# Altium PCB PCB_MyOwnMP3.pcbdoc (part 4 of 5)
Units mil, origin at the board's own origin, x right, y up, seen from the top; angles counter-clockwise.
Board outline 3605 x 4860 mil, 6 copper layers (Top Layer, Inner1, Inner2, Inner3, Inner4, Bottom Layer); 291 components, 261 nets, 1070 pads, 1658 vias.
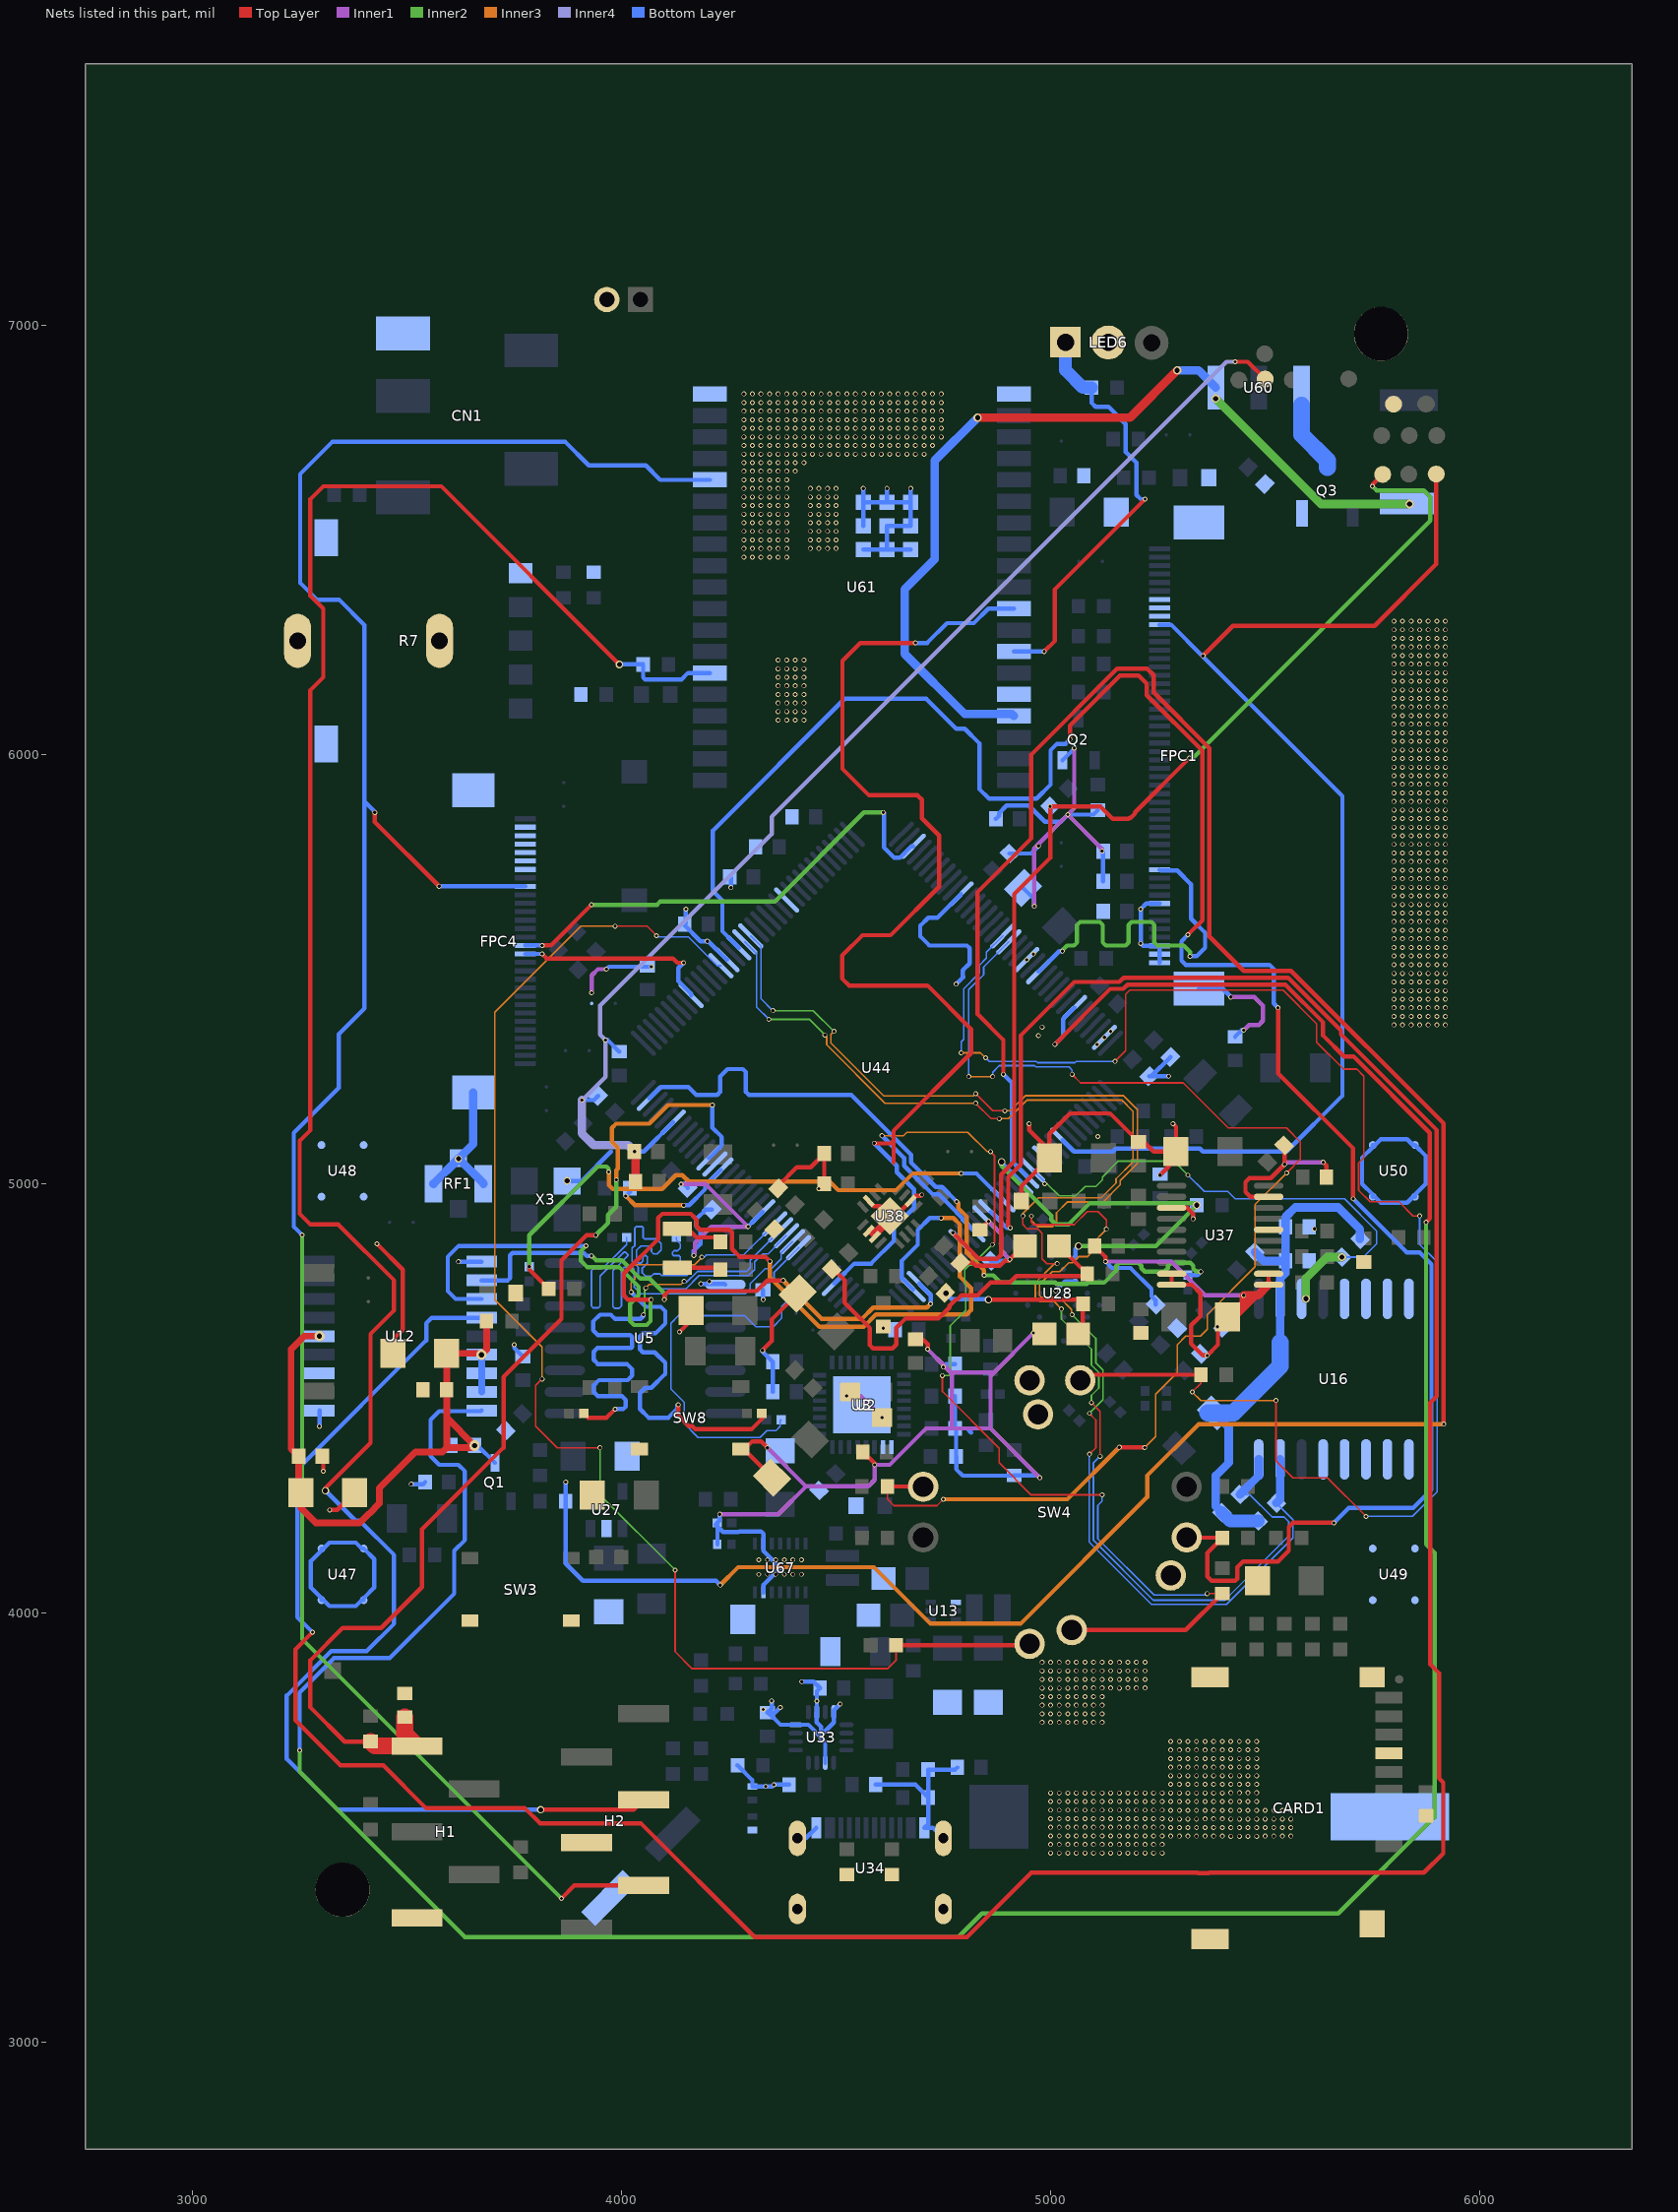
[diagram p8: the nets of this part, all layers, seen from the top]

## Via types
v1: diameter 11.42, hole 7.48, Top Layer to Bottom Layer, 1536 vias
v2: diameter 17.72, hole 11.81, Top Layer to Bottom Layer, 85 vias
v3: diameter 39.37, hole 29.53, Top Layer to Bottom Layer, 11 vias
v4: diameter 11.81, hole 7.87, Top Layer to Bottom Layer, 8 vias
v5: diameter 47.24, hole 23.62, Top Layer to Bottom Layer, 8 vias
v6: diameter 19.68, hole 11.81, Top Layer to Bottom Layer, 4 vias
v7: diameter 24.41, hole 12.2, Top Layer to Bottom Layer, 3 vias
v8: diameter 11.4, hole 7.5, Top Layer to Bottom Layer, 3 vias

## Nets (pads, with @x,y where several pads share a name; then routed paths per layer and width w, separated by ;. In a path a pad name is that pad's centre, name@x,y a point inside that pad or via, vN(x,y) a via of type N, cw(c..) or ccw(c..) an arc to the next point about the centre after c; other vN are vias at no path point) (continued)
GND: BAT1.1 C6.2 C7.2 C8.1 C9.2 C10.1 C11.2 C12.2 C13.1 C14.1 C15.1 C16.2 C17.2 C18.1 C19.2 C20.2 C21.2 C22.1 C25.1 C26.2 C28.1 C29.2 C30.2 C31.2 C32.1 C33.1 C34.2 C35.2 C37.2 C38.1 C39.1 C40.1 C41.2 C42.1 C43.1 C44.1 C45.1 C46.2 C47.2 C48.2 C49.2 C50.1 C51.1 C52.1 C53.1 C58.1 C59.1 C60.2 C61.2 C62.2 C63.2 C64.2 C65.2 C66.2 C67.2 C68.2 C69.2 C70.1 C71.2 C72.2 C75.1 C76.1 C77.1 C78.1 C79.1 C80.1 C81.1 C82.2 C84.1 C85.1 C114.1 C120.1 C121.2 C122.1 C123.2 C124.1 C126.1 C127.1 C129.1 C130.2 C131.1 C132.1 CARD1.6 CARD1.10 CARD1.11 CARD1.12 CARD1.13 CN1.1 D3.1 D4.1 FPC1.7 FPC1.8 FPC1.9 FPC1.43 FPC1.48 FPC1.49 FPC1.50 FPC1.51 FPC1.52 FPC4.24 FPC4.25 FPC4.26 FPC4.27 FPC4.28 FPC4.29 FPC4.31 FPC4.32 H1.1 H2.3 JP6.2 JP18.2 LED1.2 LED5.2 LED6.2 LED8.2 Q2.2 Q3.3 R5.2 R7.1 R7.6 R7.7 R25.1 R29.1 R32.1 R33.1 R36.1 R37.1 R40.2 R60.2 R98.2 R113.2 RF1.2 RF1.3 RF1.4 SCREW5.1 SCREW6.1 SW3.3 SW3.4 SW4.6 SW4.9 SW4.10 SW8.3 SW8.4 TP27.1 U2.2 U2.4 U3.1 U3.2 U3.33 U5.10 U6.1 U12.1 U12.10 U12.12 U13.4 U16.5 U16.6 U16.7 U16.8 U16.9 U16.10 U16.11 U16.12 U16.13 U17.2 U19.2 U20.1 U27.2 U28.B3 U30.1 U32.2 U33.4 U33.6 U33.8 U33.14 U33.17 U34.1 U34.2 U34.3 U34.4 U34.A1B12 U34.B1A12 U37.3 U37.9 U37.10 U37.11 U37.12 U37.16 U37.19 U38.2 U38.3 U38.10 U38.15 U38.17 U40.1 U44.16 U44.51 U44.61 U44.83 U44.94 U44.107 U44.120 U44.130 U47.1 U48.1 U49.1 U50.1 U61.1 U61.15 U61.38 U61.39 U67.2 U67.13 U67.15 X3.2 | length 13240.2
  Top Layer w10: C9.2@3302.56,4365 3305,4362.56 v1(3305,4330) ; v1(3320,4240) 3337.7,4240 C8.1@3377.7,4280 ; v1(3430,4860) 3490,4800 3490,4660 3467.3,4637.3 C6.2@3467.3,4605 ; v1(4135,4655) 4162.3,4682.3 C45.1@4162.3,4705 ; SW8.4@4278.11,4382.17 SW8.4@4284.16,4382.17 ; v1(4328.68,4611.61) 4328.68,4612.29 4350,4633.61 4350,4683.67 C44.1@4410.66,4744.34 ; v1(4340,4385) 4325,4400 4305,4400 4287.17,4382.17 SW8.4@4284.16,4382.17 ; C42.1@4350.66,4315.66 SW8.4@4284.16,4382.17 ; C15.1@4365.51,4989.49 4365.51,4995.51 4408.51,5038.51 4440.95,5038.51 C81.1@4472.44,5070 C84.1@4472.44,5000 ; C40.1@4562.44,4375 4562.44,4372.56 4573.31,4361.69 4576.91,4361.69 4590,4348.61 v1(4590,4345) ; U38.15@4576.32,4959.83 4576.32,4958.68 4587.33,4947.67 4602.34,4947.67 U38.17@4625.01,4925 ; C41.2@4685,4637.56 4702.44,4637.56 4713.54,4626.46 v1(4713.54,4614.61) ; v1(4700,4974.13) 4697.78,4971.92 4685.78,4971.92 U38.10@4673.69,4959.83 4638.86,4925 U38.17@4625.01,4925 ; C78.1@4789.49,4815.51 4819.49,4815.51 4825.98,4809.02 4881.62,4809.02 4893.29,4820.69 4901.81,4820.69 v1(4904.97,4823.85) 4936.12,4855 C77.1@4940.63,4855 ; C79.1@4835,4892.44 4835.39,4892.44 v1(4855.36,4912.41) ; LED5.2@4931.53,4960 4931.53,4994.23 C34.2@4997.3,5060 4997.3,5116.32 5045,5164.02 5138.54,5164.02 C33.1@5205,5097.56 5217.44,5097.56 5240,5075 C37.2@5292.3,5075 ; v1(4950,5140) 4950,5125 C34.2@4997.3,5077.7 ; v1(4960,4652.39) 4983.24,4652.39 C76.1@4985.63,4650 ; C35.2@5102.44,4855 5128.12,4829.32 v1(5128.12,4818.7) ; v1(5255,5020) 5292.3,5057.3 C37.2@5292.3,5075 ; U37.9@5281.97,4790.43 U37.10@5281.97,4764.84 5329.18,4764.84 5349.02,4745 5349.02,4691.5 5327.52,4670 5327.52,4627.48 5355,4600 v1(5365,4600) 5390,4625 5390,4665.42 v1(5388.52,4666.9) ; U37.3@5281.97,4943.98 5318.3,4943.98 5331.97,4930.3 v1(5331.97,4918.03) ; v1(5285,5140) 5292.3,5132.7 C37.2@5292.3,5075 ; C29.2@5417.7,4690 5433.19,4690 5468.35,4725.16 ; v1(5450,4740) 5464.84,4725.16 5468.35,4725.16 ; 5483.19,4740 5468.35,4725.16 ; U37.11@5508.03,4764.84 U37.12@5508.03,4790.43 ; U37.19@5508.03,4969.57 5465.43,4969.57 5453.94,4981.06 5453.94,5003.94 5463.31,5013.31 5513.31,5013.31 v1(5545,5045) 5545,5088.98 C75.1@5544.49,5089.49 ; v1(5635,5050) 5642.56,5042.44 C30.2@5642.56,5015 ; U38.17@4625.01,4925 4625.01,4911.14 U38.3@4590.18,4876.31 U38.2@4576.32,4890.17 4590.18,4890.17 U38.17@4625.01,4925
  Top Layer w19.68: C29.2@5417.7,4690 5450,4722.3 v1(5450,4740) 5483.19,4740 U37.11@5508.03,4764.84
  Inner1 w10: v1(3930.47,5444.84) 3930.47,5485.47 3945,5500 v1@3964.87,5500 ; v1(4138.75,4999.04) 4195.96,4999.04 v1(4295,4900) 4209.13,4900 4170.71,4861.59 4170.71,4835.36 v1(4168.31,4832.95) ; v1(4228.78,4230) 4365,4230 4430,4295 ; v1(4340,4385) 4430,4295 ; v1(4524.43,4505.72) 4557.15,4505.72 v1(4607.4,4455.47) ; v1(4713.54,4614.61) v1@4755.19,4572.95 ; v1(4749.88,4572.95) v1@4755.19,4572.95 ; v1(4855.36,4912.41) 4884.49,4883.28 4884.49,4844.33 v1(4904.97,4823.85) ; v1(4960,4652.39) 4867.45,4559.84 ; v1(4961.87,5646.29) 4961.87,5781.87 v1@4971.63,5791.63 ; v1(4971.63,5786.98) v1@4971.63,5791.63 ; v1(4975,4315) 4860,4430 ; v1(5055,6015) 5055,5875 v1(5040,5860) ; v1(5120,5775) 5120,5780 v1(5040,5860) ; v1(5128.12,4818.7) 5281.3,4818.7 5360,4740 v1(5450,4740) ; v1(5420,5435) 5475,5435 5495,5415 5495,5380 5485,5370 5462.07,5370 v1(5450,5357.93) ; v1(5545,5045) 5550,5050 v1(5635,5050) ; 4430,4295 4575,4295 4590,4310 v1(4590,4345) 4625,4345 4710,4430 4770.17,4430 ; v1@4755.19,4572.95 4770.17,4557.97 ; 4770.17,4430 4770.17,4557.97 ; 4770.17,4430 4860,4430 ; 4770.17,4557.97 4772.05,4559.84 4860,4559.84 ; 4860,4430 4860,4552.39 ; 4860,4552.39 4860,4559.84 ; 4860,4552.39 4867.45,4559.84 ; 4860,4559.84 4867.45,4559.84 ; v1@4971.63,5791.63 v1(5040,5860)
  Bottom Layer w10: v1(3296.02,4435) U12.10@3296.02,4471.77 ; U47.1@3399.19,4150.18 3394.45,4150.17 3380.64,4163.98 3319.36,4163.98 3305.55,4150.17 U47.1@3300.79,4150.17 3300.79,4145.41 3276.02,4120.64 3276.02,4059.36 3300.79,4034.59 U47.1@3300.79,4029.83 3305.55,4029.83 3319.36,4016.02 3380.64,4016.02 3394.45,4029.83 U47.1@3399.21,4029.83 3399.21,4034.59 3423.98,4059.36 3423.98,4125.39 U47.1@3399.19,4150.18 ; v1(3510,4300) 3537.44,4300 C21.2@3542.44,4305 ; v1(3620,4818.23) U12.1@3673.98,4818.23 ; v1(3750,4625) 3750,4617.56 C22.1@3770,4597.56 ; v2(3873.31,5006.62) 3907.09,5006.62 JP18.2@3975.47,5075 ; v1(3964.93,5499.93) 3970.59,5505.59 v1(4069.6,5505.59) ; v1(4138.75,4999.04) 4145.96,4999.04 C64.2@4154.49,4990.51 ; v1(4150,5640) 4150,5607.56 C63.2@4147.44,5605 4147.44,5601.8 4184.24,5565 v1(4200,5565) 4202.56,5565 U44.51@4245.62,5521.94 ; v1(4168.31,4832.95) 4168.31,4843.97 4184.16,4859.82 4184.16,4890.18 4175,4899.34 4175.09,4918.78 4195.8,4939.49 C65.2@4210.51,4939.49 ; v1(4185,4766.69) 4240.34,4766.69 U5.10@4242.02,4765.01 ; C127.1@4223.46,4160 R113.2@4223.46,4201.54 ; v1(4228.78,4230) 4228.78,4215.82 R113.2@4222.96,4210 R113.2@4223.46,4209.5 ; C62.2@4252.44,5715 4255,5712.44 v1(4255,5690) ; U20.1@4270.34,3645 4305,3610.34 D3.1@4305,3595.75 v1(4335.73,3595.75) 4350.75,3595.75 v1(4355,3600) U6.1@4390.34,3600 ; v1(4295,4900) 4329.13,4934.13 U44.16@4329.13,4934.54 ; v1(4328.68,4611.61) 4328.68,4608.76 C46.2@4352.44,4585 C43.1@4352.44,4515 ; v1(4330,4730) C58.1@4330,4752.56 ; U67.13@4330.63,4047.91 4330.63,4065.63 U67.15@4370,4105 4330.63,4144.37 U67.2@4330.63,4162.09 4330.63,4184.37 4325,4190 4274.34,4190 4272.72,4188.39 4236.61,4188.39 R113.2@4223.46,4201.54 ; v1(4350,3795) 4350,3777.56 C85.1@4340,3767.56 C85.1@4342.44,3767.56 ; v1(4370,3780) 4357.56,3767.56 C85.1@4342.44,3767.56 ; U34.2@4409.92,3475.08 4429.61,3475.08 U34.B1A12@4454.02,3499.49 ; v1(4420,3840) 4447.44,3840 C51.1@4462.44,3825 4455.17,3817.73 v1(4455.17,3794.75) U33.6@4455.17,3769.05 4455,3768.88 4455,3745 4465.01,3734.99 U33.17@4465.01,3715.02 ; U33.14@4474.85,3650.94 4474.85,3700.15 U33.17@4465.01,3709.99 ; v1(4509.54,3787.69) 4495,3773.15 4495,3745.01 U33.17@4465.01,3715.02 ; U61.39@4563.54,6477.4 U61.39@4618.66,6477.4 ; U61.39@4563.54,6532.52 U61.39@4563.54,6587.64 ; v1(4563.54,6620) U61.39@4563.54,6587.64 ; C50.1@4592.56,3600 4685,3600 R32.1@4714.66,3570.34 ; v1(4618.66,6620) U61.39@4618.66,6587.64 ; U61.39@4673.78,6477.4 U61.39@4618.66,6477.4 ; v1(4673.78,6620) U61.39@4673.78,6587.64 ; v1(4749.88,4572.95) 4756.93,4580 C47.2@4777.56,4580 ; U34.1@4750.08,3475.08 4725.67,3499.49 U34.A1B12@4705.99,3499.49 4714.66,3508.16 R32.1@4714.66,3570 R32.1@4714.66,3570.34 ; C80.1@4777.56,4505 C49.2@4777.56,4430 ; v1(4780,5465) 4796.06,5481.06 4796.06,5482.65 4795.63,5483.09 4795.63,5496.91 4796.06,5497.35 4796.06,5498 4811.22,5513.16 4811.22,5548.78 4805,5555 4717.61,5555 4695.98,5576.62 4695.98,5601.16 4714.82,5620 4736.21,5620 U44.83@4791.27,5675.06 ; C12.2@4782.44,3640 4777.44,3635 R33.1@4714.66,3635 R32.1@4714.66,3570.34 ; 4815,4420 4805,4430 C49.2@4777.56,4430 ; C67.2@4860.51,4820.51 4901.53,4820.51 4901.7,4820.69 4901.81,4820.69 v1(4904.97,4823.85) ; C122.1@4872.44,5850 4880,5857.56 4880,5863.56 4897.5,5881.06 4948.94,5881.06 4986.61,5843.39 5023.39,5843.39 v1(5040,5860) 5099.66,5860 R60.2@5110,5870.34 ; C123.2@4904.49,5769.49 4954.13,5769.49 v1(4971.63,5786.98) ; C25.1@4935.66,5689.34 4961.87,5663.13 v1(4961.87,5646.29) ; v1(4975,4315) 4969.66,4320.34 U40.1@4915,4320.34 4914.66,4320 4795,4320 4780,4335 4780,4364.66 R29.1@4779.66,4365 4779.66,4427.9 C49.2@4777.56,4430 ; v1(5012.01,4750.23) 5012.72,4750.94 5012.72,4752.16 5022.84,4762.28 5023.04,4762.28 5033.6,4772.84 U28.B3@5057.84,4772.84 ; Q2.2@5027.6,5986.38 5055,6013.78 v1(5055,6015) ; v1(5120,5775) 5122.44,5772.56 C19.2@5122.44,5705 ; v1(5128.12,4818.7) 5142.81,4804.02 5185.98,4804.02 5235,4755 5235,4738.22 5244.77,4728.45 C71.2@5244.77,4718.45 ; C60.2@5229.49,5250.51 C60.2@5234.49,5250.51 ; FPC1.50@5254.25,5515.15 FPC1.49@5254.24,5534.82 FPC1.48@5254.25,5554.5 5215.5,5554.5 v1(5210,5560) v1(5210,5640) 5222.89,5652.89 FPC1.43@5254.3,5652.89 ; v1(5275,5250.51) C60.2@5234.49,5250.51 ; C52.1@5279.49,5295.51 C60.2@5234.49,5250.51 ; FPC1.52@5345.88,5454.46 5400.54,5454.46 v1(5420,5435) ; C59.1@5430,5342.56 5445.37,5357.93 v1(5450,5357.93) ; U50.1@5849.19,5090.18 5844.45,5090.17 5830.64,5103.98 5769.36,5103.98 5755.55,5090.17 U50.1@5750.79,5090.17 5750.79,5085.41 5726.02,5060.64 5726.02,4999.36 5750.79,4974.59 U50.1@5750.79,4969.83 5755.55,4969.83 5769.36,4956.02 5830.64,4956.02 5844.45,4969.83 U50.1@5849.21,4969.83 5849.21,4974.59 5873.98,4999.36 5873.98,5065.39 U50.1@5849.19,5090.18 ; R113.2@4223.46,4201.54 4219.48,4205.52 R113.2@4223.46,4209.5 ; R113.2@4223.46,4201.54 R113.2@4223.46,4209.5 ; C85.1@4342.44,3767.56 4370.48,3739.52 U33.4@4405.95,3739.52 4435.48,3739.52 U33.17@4465.01,3709.99 ; U33.17@4465.01,3709.99 U33.17@4465.01,3715.02 ; U61.39@4563.54,6587.64 U61.39@4618.66,6587.64 ; U61.39@4618.66,6477.4 U61.39@4618.66,6532.52 U61.39@4673.78,6532.52 U61.39@4673.78,6587.64 ; U61.39@4618.66,6587.64 U61.39@4673.78,6587.64
  Bottom Layer w19.68: RF1.2@3561.93,5000 v2(3620,5058.07) ; FPC4.32@3654.47,5213.04 3654.47,5092.54 RF1.4@3620.49,5058.56 ; RF1.3@3678.07,5000 3678.07,5000.98 RF1.4@3620.49,5058.56 ; v2(3620,5058.07) RF1.4@3620,5059.05 RF1.4@3620.49,5058.56 ; v2(3620,5058.07) RF1.4@3620.49,5058.56
  other v1: 5000,3440.67 5020,3440.67 5040,3440.67 5060,3440.67 5080,3440.67 5100,3440.67 5120,3440.67 5140,3440.67 5160,3440.67 5180,3440.67 5200,3440.67 5220,3440.67 5240,3440.67 5260,3440.67 5000,3460.67 5020,3460.67 5040,3460.67 5060,3460.67 5080,3460.67 5100,3460.67 5120,3460.67 5140,3460.67 5160,3460.67 5180,3460.67 5200,3460.67 5220,3460.67 5240,3460.67 5260,3460.67 5280,3480 5300,3480 5320,3480 5340,3480 5360,3480 5380,3480 5400,3480 5420,3479.77 5440,3479.77 5460,3479.77 5480,3479.77 5500,3480 5520,3480 5540,3480 5560,3480 5000,3480.67 5020,3480.67 5040,3480.67 5060,3480.67 5080,3480.67 5100,3480.67 5120,3480.67 5140,3480.67 5160,3480.67 5180,3480.67 5200,3480.67 5220,3480.67 5240,3480.67 5260,3480.67 5280,3500 5300,3500 5320,3500 5340,3500 5360,3500.23 5380,3500.23 5400,3500.23 5420,3499.77 5440,3499.77 5460,3499.77 5480,3499.77 5500,3500 5520,3500 5540,3500 5560,3500 5000,3500.67 5020,3500.67 5040,3500.67 5060,3500.67 5080,3500.67 5100,3500.67 5120,3500.67 5140,3500.67 5160,3500.67 5180,3500.67 5200,3500.67 5220,3500.67 5240,3500.67 5260,3500.67 5280,3520 5300,3520 5320,3520 5340,3520 5360,3520.23 5380,3520.23 5400,3520.23 5420,3519.77 5440,3519.77 5460,3519.77 5480,3519.77 5500,3520 5520,3520 5540,3520 5560,3520 5000,3520.67 5020,3520.67 5040,3520.67 5060,3520.67 5080,3520.67 5100,3520.67 5120,3520.67 5140,3520.67 5160,3520.67 5180,3520.67 5200,3520.67 5220,3520.67 5240,3520.67 5260,3520.67 5280,3540 5300,3540 5320,3540 5340,3540 5360,3540.23 5380,3540.23 5400,3540.23 5420,3540 5440,3540 5460,3540 5480,3540 5500,3540 5520,3540 5540,3540 5560,3540 5000,3540.67 5020,3540.67 5040,3540.67 5060,3540.67 5080,3540.67 5100,3540.67 5120,3540.67 5140,3540.67 5160,3540.67 5180,3540.67 5200,3540.67 5220,3540.67 5240,3540.67 5260,3540.67 5000,3560.67 5020,3560.67 5040,3560.67 5060,3560.67 5080,3560.67 5100,3560.67 5120,3560.67 5140,3560.67 5160,3560.67 5180,3560.67 5200,3560.67 5220,3560.67 5240,3560.67 5260,3560.67 5280,3560.67 5300,3560.67 5320,3560.67 5340,3560.67 5360,3560.67 5380,3560.67 5400,3560.67 5419.96,3560.91 5439.96,3560.91 5459.96,3560.91 5479.96,3560.91 5000,3580.67 5020,3580.67 5040,3580.67 5060,3580.67 5080,3580.67 5100,3580.67 5120,3580.67 5140,3580.67 5160,3580.67 5180,3580.67 5200,3580.67 5220,3580.67 5240,3580.67 5260,3580.67 5280,3580.67 5300,3580.67 5320,3580.67 5340,3580.67 5360,3580.67 5380,3580.67 5400,3580.67 5419.96,3580.91 5439.96,3580.91 5459.96,3580.91 5479.96,3580.91 5280,3600.67 5300,3600.67 5320,3600.67 5340,3600.67 5360,3600.67 5380,3600.67 5400,3600.67 5419.96,3600.91 5439.96,3600.91 5459.96,3600.91 5479.96,3600.91 5280,3620.67 5300,3620.67 5320,3620.67 5340,3620.67 5360,3620.67 5380,3620.67 5400,3620.67 5419.96,3620.91 5439.96,3620.91 5459.96,3620.91 5479.96,3620.91 5280,3640.67 5300,3640.67 5320,3640.67 5340,3640.67 5360,3640.67 5380,3640.67 5400,3640.67 5419.73,3640.91 5439.73,3640.91 5459.73,3640.91 5479.96,3640.91 5280,3660.67 5300,3660.67 5320,3660.67 5340,3660.67 5360,3660.67 5380,3660.67 5400,3660.67 5419.73,3660.91 5439.73,3660.91 5459.73,3660.91 5479.96,3660.91 5280,3680.67 5300,3680.67 5320,3680.67 5340,3680.67 5360,3680.67 5380,3680.67 5400,3680.67 5419.73,3680.91 5439.73,3680.91 5459.73,3680.91 5479.96,3680.91 5280,3700.67 5300,3700.67 5320,3700.67 5340,3700.67 5360,3700.67 5380,3700.67 5400,3700.67 5419.73,3700.91 5439.73,3700.91 5459.73,3700.91 5479.96,3700.91 4980,3745 5000,3745 5020,3745 5040,3745 5060,3745 5080,3745 5100,3745 5120,3745 4980,3765 5000,3765 5020,3765 5040,3765 5060,3765 5080,3765 5100,3765 5120,3765 4330,3775 4980,3785 5000,3785 5020,3785 5040,3785 5060,3785 5080,3785 5100,3785 5120,3785 4980,3805 5000,3805 5020,3805 5040,3805 5060,3805 5080,3805 5100,3805 5120,3805 4980,3825 5000,3825 5020,3825 5040,3825 5060,3825.23 5080,3825.23 5100,3825.23 5120,3825.23 5140,3825.23 5160,3825 5180,3825.23 5200,3825.23 5220,3825.23 4980,3845 5000,3845 5020,3845 5040,3845 5060,3845.23 5080,3845.23 5100,3845.23 5120,3845.23 5140,3845.23 5160,3845 5180,3845.23 5200,3845.23 5220,3845.23 4980,3865 5000,3865 5020,3865 5040,3865 5060,3865.23 5080,3865.23 5100,3865.23 5120,3865.23 5140,3865.23 5160,3865 5180,3865.23 5200,3865.23 5220,3865.23 4980,3885 5000,3885 5020,3885 5040,3885 5060,3885.23 5080,3885.23 5100,3885.23 5120,3885.23 5140,3885.23 5160,3885 5180,3885.23 5200,3885.23 5220,3885.23 4320,4090 4340,4090 4359.34,4090 4379.34,4090 4399.34,4090 4419.34,4090 4320,4123.63 4340,4123.63 4359.34,4123.63 4379.34,4123.63 4399.34,4123.63 4419.34,4123.63 4610,4663.5 4204.92,4772.17 5615,4895 4460,4988.31 5110,5110 5108.62,5324.29 5125.33,5340.99 4971.69,5345.23 5140,5355 4980,5365 5800,5370 5820,5370 5840,5370 5860,5370 5880,5370 5900,5370 5920,5370 5800,5390 5820,5390 5840,5390 5860,5390 5880,5390 5900,5390 5920,5390 5800,5410 5820,5410 5840,5410 5860,5410 5880,5410 5900,5410 5920,5410 5800,5430 5820,5430 5840,5430 5860,5430 5880,5430 5900,5430 5920,5430 5800,5450 5820,5450 5840,5450 5860,5450 5880,5450 5900,5450 5920,5450 5800,5470 5820,5470 5840,5470 5860,5470 5880,5470 5900,5470 5920,5470 5800,5490 5820,5490 5840,5490 5860,5490 5880,5490 5900,5490 5920,5490 5800,5510 5820,5510 5840,5510 5860,5510 5880,5510 5900,5510 5920,5510 4944.38,5521.94 5800,5530.67 5820,5530.67 5840,5530.67 5860,5530.67 5880,5530.67 5900,5530.67 5920,5530.67 4960,5535 5800,5550.67 5820,5550.67 5840,5550.67 5860,5550.67 5880,5550.67 5900,5550.67 5920,5550.67 5800,5570.67 5820,5570.67 5840,5570.67 5860,5570.67 5880,5570.67 5900,5570.67 5920,5570.67 5800,5590.67 5820,5590.67 5840,5590.67 5860,5590.67 5880,5590.67 5900,5590.67 5920,5590.67 5800,5610.67 5820,5610.67 5840,5610.67 5860,5610.67 5880,5610.67 5900,5610.67 5920,5610.67 5800,5630.67 5820,5630.67 5840,5630.67 5860,5630.67 5880,5630.67 5900,5630.67 5920,5630.67 5800,5650.67 5820,5650.67 5840,5650.67 5860,5650.67 5880,5650.67 5900,5650.67 5920,5650.67 5800,5670.67 5820,5670.67 5840,5670.67 5860,5670.67 5880,5670.67 5900,5670.67 5920,5670.67 5800,5690.67 5820,5690.67 5840,5690.67 5860,5690.67 5880,5690.67 5900,5690.67 5920,5690.67 5800,5710.67 5820,5710.67 5840,5710.67 5860,5710.67 5880,5710.67 5900,5710.67 5920,5710.67 5800,5730.67 5820,5730.67 5840,5730.67 5860,5730.67 5880,5730.67 5900,5730.67 5920,5730.67 5800,5750.67 5820,5750.67 5840,5750.67 5860,5750.67 5880,5750.67 5900,5750.67 5920,5750.67 5800,5770.67 5820,5770.67 5840,5770.67 5860,5770.67 5880,5770.67 5900,5770.67 5920,5770.67 5800,5790.67 5820,5790.67 5840,5790.67 5860,5790.67 5880,5790.67 5900,5790.67 5920,5790.67 5800,5810.67 5820,5810.67 5840,5810.67 5860,5810.67 5880,5810.67 5900,5810.67 5920,5810.67 5800,5830.67 5820,5830.67 5840,5830.67 5860,5830.67 5880,5830.67 5900,5830.67 5920,5830.67 5800,5850.67 5820,5850.67 5840,5850.67 5860,5850.67 5880,5850.67 5900,5850.67 5920,5850.67 5800,5870.67 5820,5870.67 5840,5870.67 5860,5870.67 5880,5870.67 5900,5870.67 5920,5870.67 5800,5890.67 5820,5890.67 5840,5890.67 5860,5890.67 5880,5890.67 5900,5890.67 5920,5890.67 5800,5910.67 5820,5910.67 5840,5910.67 5860,5910.67 5880,5910.67 5900,5910.67 5920,5910.67 5800,5930.67 5820,5930.67 5840,5930.67 5860,5930.67 5880,5930.67 5900,5930.67 5920,5930.67 5800,5950.67 5820,5950.67 5840,5950.67 5860,5950.67 5880,5950.67 5900,5950.67 5920,5950.67 5800,5970.67 5820,5970.67 5840,5970.67 5860,5970.67 5880,5970.67 5900,5970.67 5920,5970.67 5800,5990.67 5820,5990.67 5840,5990.67 5860,5990.67 5880,5990.67 5900,5990.67 5920,5990.67 5800,6010.67 5820,6010.67 5840,6010.67 5860,6010.67 5880,6010.67 5900,6010.67 5920,6010.67 5800,6030.67 5820,6030.67 5840,6030.67 5860,6030.67 5880,6030.67 5900,6030.67 5920,6030.67 5800,6050.67 5820,6050.67 5840,6050.67 5860,6050.67 5880,6050.67 5900,6050.67 5920,6050.67 5800,6070.67 5820,6070.67 5840,6070.67 5860,6070.67 5880,6070.67 5900,6070.67 5920,6070.67 4365,6080 4385,6080 4405,6080 4425,6080 5800,6090.67 5820,6090.67 5840,6090.67 5860,6090.67 5880,6090.67 5900,6090.67 5920,6090.67 4365,6100 4385,6100 4405,6100 4425,6100 5800,6110.67 5820,6110.67 5840,6110.67 5860,6110.67 5880,6110.67 5900,6110.67 5920,6110.67 4365,6120 4385,6120 4405,6120 4425,6120 5800,6130.67 5820,6130.67 5840,6130.67 5860,6130.67 5880,6130.67 5900,6130.67 5920,6130.67 4365,6140 4385,6140 4405,6140 4425,6140 5800,6150.67 5820,6150.67 5840,6150.67 5860,6150.67 5880,6150.67 5900,6150.67 5920,6150.67 4365,6160 4385,6160 4405,6160 4425,6160 5800,6170.67 5820,6170.67 5840,6170.67 5860,6170.67 5880,6170.67 5900,6170.67 5920,6170.67 4365,6180 4385,6180 4405,6180 4425,6180 5800,6190.67 5820,6190.67 5840,6190.67 5860,6190.67 5880,6190.67 5900,6190.67 5920,6190.67 4365,6200 4385,6200 4405,6200 4425,6200 5800,6210.67 5820,6210.67 5840,6210.67 5860,6210.67 5880,6210.67 5900,6210.67 5920,6210.67 4365,6220 4385,6220 4405,6220 4425,6220 5800,6230.67 5820,6230.67 5840,6230.67 5860,6230.67 5880,6230.67 5900,6230.67 5920,6230.67 5800,6250.67 5820,6250.67 5840,6250.67 5860,6250.67 5880,6250.67 5900,6250.67 5920,6250.67 5800,6270.67 5820,6270.67 5840,6270.67 5860,6270.67 5880,6270.67 5900,6270.67 5920,6270.67 5800,6290.67 5820,6290.67 5840,6290.67 5860,6290.67 5880,6290.67 5900,6290.67 5920,6290.67 5800,6310.67 5820,6310.67 5840,6310.67 5860,6310.67 5880,6310.67 5900,6310.67 5920,6310.67 4285,6460 4305,6460 4325,6460 4345,6460 4365,6460 4385,6460 4285,6480 4305,6480 4325,6480 4345,6480 4365,6480 4385,6480 4440,6480 4460,6480 4480,6480 4500,6480 4285,6500 4305,6500 4325,6500 4345,6500 4365,6500 4385,6500 4440,6500 4460,6500 4480,6500 4500,6500 4285,6520 4305,6520 4325,6520 4345,6520 4365,6520 4385,6520 4440,6520 4460,6520 4480,6520 4500,6520 4285,6540 4305,6540 4325,6540 4345,6540 4365,6540 4385,6540 4440,6540 4460,6540 4480,6540 4500,6540 4285,6560 4305,6560 4325,6560 4345,6560 4365,6560 4385,6560 4440,6560 4460,6560 4480,6560 4500,6560 4285,6580 4305,6580 4325,6580 4345,6580 4365,6580 4385,6580 4440,6580 4460,6580 4480,6580 4500,6580 4285,6600 4305,6600 4325,6600 4345,6600 4365,6600 4385,6600 4440,6600 4460,6600 4480,6600 4500,6600 4285,6620 4305,6620 4325,6620 4345,6620 4365,6620 4385,6620 4440,6620 4460,6620 4480,6620 4500,6620 4285,6640 4305,6640 4325,6640 4345,6640 4365,6640 4385,6640 4285,6660 4305,6660 4325,6660 4345,6660 4365,6660 4385,6660 4405,6660 4285,6680 4305,6680 4325,6680 4345,6680 4365,6680 4385,6680 4405,6680 4425,6680 4285,6700 4305,6700 4325,6700 4345,6700 4365,6700 4385,6700 4405,6700 4425,6700 4445,6700 4465,6700 4485,6700 4505,6700 4525,6700 4545,6700 4565,6700 4585,6700 4605,6700 4625,6700 4645,6700 4665,6700 4685,6700 4705,6700 4285,6720 4305,6720 4325,6720 4345,6720 4365,6720 4385,6720 4405,6720 4425,6720 4445,6720 4465,6720 4485,6720 4505,6720 4525,6720 4545,6720 4565,6720 4585,6720 4605,6720 4625,6720 4645,6720 4665,6720 4685,6720 4705,6720 4725,6720 4285,6740 4305,6740 4325,6740 4345,6740 4365,6740 4385,6740 4405,6740 4425,6740 4445,6740 4465,6740 4485,6740 4505,6740 4525,6740 4545,6740 4565,6740 4585,6740 4605,6740 4625,6740 4645,6740 4665,6740 4685,6740 4705,6740 4725,6740 4745,6740 4285,6760 4305,6760 4325,6760 4345,6760 4365,6760 4385,6760 4405,6760 4425,6760 4445,6760 4465,6760 4485,6760 4505,6760 4525,6760 4545,6760 4565,6760 4585,6760 4605,6760 4625,6760 4645,6760 4665,6760 4685,6760 4705,6760 4725,6760 4745,6760 4285,6780 4305,6780 4325,6780 4345,6780 4365,6780 4385,6780 4405,6780 4425,6780 4445,6780 4465,6780 4485,6780 4505,6780 4525,6780 4545,6780 4565,6780 4585,6780 4605,6780 4625,6780 4645,6780 4665,6780 4685,6780 4705,6780 4725,6780 4745,6780 4285,6800 4305,6800 4325,6800 4345,6800 4365,6800 4385,6800 4405,6800 4425,6800 4445,6800 4465,6800 4485,6800 4505,6800 4525,6800 4545,6800 4565,6800 4585,6800 4605,6800 4625,6800 4645,6800 4665,6800 4685,6800 4705,6800 4725,6800 4745,6800 4285,6820 4305,6820 4325,6820 4345,6820 4365,6820 4385,6820 4405,6820 4425,6820 4445,6820 4465,6820 4485,6820 4505,6820 4525,6820 4545,6820 4565,6820 4585,6820 4605,6820 4625,6820 4645,6820 4665,6820 4685,6820 4705,6820 4725,6820 4745,6820 4285,6840 4305,6840 4325,6840 4345,6840 4365,6840 4385,6840 4405,6840 4425,6840 4445,6840 4465,6840 4485,6840 4505,6840 4525,6840 4545,6840 4565,6840 4585,6840 4605,6840 4625,6840 4645,6840 4665,6840 4685,6840 4705,6840 4725,6840 4745,6840
GNDA: C54.1 C55.2 C56.2 C57.1 JP18.1 TP15.1 U44.31 | length 2952.1
  Top Layer w10: v1(5430,6915) 5459.47,6915 TP15.1@5499.84,6874.63
  Top Layer w19.68: C55.2@4029.88,5075 4032.44,5072.44 C54.1@4032.44,5005
  Inner4 w10: v1(3907.87,5195) 3908.61,5195 3962.61,5249 v1(3962.61,5335) 3950,5347.61 3950,5415 4350,5815 4350,5855 5410,6915 v1(5430,6915)
  Inner4 w19.68: v1(3907.87,5195) 3907.87,5117.13 3935,5090 4015.59,5090 v1(4030.59,5075)
  Bottom Layer w10: v1(3907.87,5195) 3936.02,5195 C57.1@3945.51,5204.49 ; v1(3962.61,5335) 3967.56,5335 C56.2@3995,5307.56 ; v1(4030.59,5075) 4052.02,5075 U44.31@4120.35,5143.33
GPS_PPS: U12.4 U44.129 | length 7585.6
  Top Layer w10: v1(3280,3955) 3240,3915 3240,3750 3345,3645 3445,3645 3545,3545 3775,3545 3810,3510 4045,3510 4310,3245 4805,3245 4955,3395 5342.55,3395 5343.3,3394.25 5368.7,3394.25 5369.45,3395 5870,3395 5915,3440 5915,3605 5905,3615 5905,3860 5885,3880 5885,4490 5900,4505 5900,5125 5676.69,5348.31 5676.69,5356.91 5553.61,5480 5170,5480 5160,5470 5055,5470 4930.98,5345.98 4930.98,5045.32 4901.18,5015.51 4901.18,4914.79 4900.81,4914.41 4900.81,4902.4 v1(4906.18,4897.03)
  Bottom Layer w10: v1(3280,3955) 3244.53,3990.47 3244.53,4133.83 3245,4134.3 3245,4335 3545,4635 3545,4675 3557.5,4687.5 3673.17,4687.5 U12.4@3673.98,4688.31 ; U44.129@4860.87,4934.54 4898.38,4897.03 v1(4906.18,4897.03)
GPS_RST: U12.9 U44.102 | length 6966.2
  Top Layer w10: v1(5010,5325) 5139.02,5454.02 5169.29,5454.02 5179.29,5464.02 5546.99,5464.02 5635,5376 5635,5345 5683.8,5296.2 5706.2,5296.2 5883.7,5118.7 5883.7,4918.7 v1(5875,4910)
  Inner2 w10: v1(3250,3680) 3250,3630 3635,3245 4785,3245 4840,3300 5670,3300 5895,3525 5895,4140 5875,4160 v1(5875,4910)
  Bottom Layer w10: v1(3250,3680) 3250,3815 3330,3895 3460,3895 3610,4045 3610,4145 3635,4170 3635,4330 3620,4345 3575,4345 3555,4365 3555,4450 3575,4470 3672.21,4470 U12.9@3673.98,4471.77 ; v1(5010,5325) 5029.21,5344.21 5029.21,5384.06 U44.102@5055.74,5410.59
GPS_RXD: U12.3 U44.142 | length 2578.5
  Top Layer w10: v1(4069.11,4730) 4015,4730 4005,4740 4005,4790.55 4085,4870.55 4085,4920 4095,4930 4161.4,4930 4168.94,4922.46 4168.94,4922.26 4175.09,4916.11 4175.09,4901.01 4183.11,4892.99 4250.77,4892.99 4257.2,4886.56 4257.2,4847.79 4274.99,4830 4335.05,4830 v1(4345.92,4819.13)
  Inner2 w10: v1(3917.5,4855.29) 3905,4842.79 3905,4820.98 3920,4805.98 3994.02,4805.98 4040,4760 4040,4740 4020,4720 4020,4680 4029.02,4670.98 4058.7,4670.98 4067.72,4680 4067.72,4728.61 v1(4069.11,4730)
  Inner3 w10: v1(4345.92,4819.13) 4345.92,4782.13 4461.52,4666.53 4564.13,4666.53 4593.12,4695.52 4804.39,4695.52 4815,4706.12 4815,4756.91 4788.72,4783.2 4788.72,4904.81 4773.53,4920 v1(4744.94,4920)
  Bottom Layer w10: U12.3@3673.98,4731.61 3613.39,4731.61 3595,4750 3595,4830 3620.29,4855.29 v1(3917.5,4855.29) ; U44.142@4679.91,4753.59 4653.39,4780.11 4653.39,4820.88 4690.38,4857.87 4690.38,4892.07 4718.51,4920.2 4744.74,4920.2 v1(4744.94,4920)
GPS_TG: R21.1 U44.123 | length 6095.4
  Top Layer w10: v1(4890,5255) 4890,5335 4830,5395 4830,5680 4955,5805 4955,6000 5155,6200 5225,6200 5240,6185 5240,6145 5370,6015 5370,5575.98 5450,5495.98 5560.23,5495.98 5915.98,5140.23 v1(5915.98,4440)
  Inner3 w10: v1(4230,4065) 4271.69,4106.69 4588.31,4106.69 4720,3975 4930,3975 5225,4270 5225,4320 5345,4440 v1(5915.98,4440)
  Bottom Layer w10: v1(3870,4305) 3870,4260.34 R21.1@3869.66,4260 3870,4259.66 3870,4115 3910,4075 4220,4075 v1(4230,4065) ; v1(4890,5255) 4910,5235 4910,5052.44 U44.123@4944.38,5018.06
GPS_TXD: U12.2 U44.141 | length 1291.8
  Top Layer w10: v1(4100,4730) 4100,4740 4110,4750 4315,4750 4339.78,4774.78 v1(4376.88,4774.78)
  Inner2 w10: v1(3930,4831.69) 3931.26,4831.69 3940.98,4821.97 4000.64,4821.97 4043.79,4778.81 4065.98,4778.81 4100,4744.79 v1(4100,4730)
  Inner3 w10: v1(4376.88,4774.78) 4466.14,4685.52 4560.52,4685.52 4586.5,4711.5 4711.5,4711.5 v1(4720,4720)
  Bottom Layer w10: U12.2@3673.98,4774.92 3734.92,4774.92 3740,4780 3740,4832.93 3746.16,4839.09 3910.09,4839.09 3910.77,4838.4 3911.57,4838.43 3912.72,4837.28 3913.16,4837.28 3918.76,4831.69 v1(3930,4831.69) ; U44.141@4693.83,4767.51 4720.35,4740.99 4720.35,4722.82 4720,4722.47 v1(4720,4720)
GPS_VCC: C6.1 C7.1 C8.2 C9.1 C14.2 Q1.3 R23.1 U12.6 U12.7 U12.8 U12.14 | length 1578.5
  Top Layer w15.75: C8.2@3247.3,4310 3247.44,4310.14 C9.1@3247.44,4365 ; C9.1@3247.4,4357.6 C9.1@3247.44,4365 3230,4382.4 3230,4615 3260,4645 v7(3296.02,4645) ; C8.2@3252.3,4280 3252.3,4245 3287.3,4210 3390,4210 3412.13,4232.13 3412.67,4232.13 3435.69,4255.14 3435.69,4290.69 3520,4375 3582.56,4375 3592.56,4385 ; C7.1@3592.56,4520 3592.56,4455 ; C7.1@3592.56,4520 C6.1@3592.7,4605 3674,4605 v7(3673.98,4601.69) 3685.34,4613.05 R23.1@3685.34,4680 ; v7(3657.56,4390) 3592.56,4454.99 ; v7(3657.56,4390) 3652.6,4385 3592.56,4385 ; 3592.56,4385 3592.56,4454.99
  Bottom Layer w10: v7(3657.56,4390) 3664.69,4390 Q1.3@3705,4349.69
  Bottom Layer w15.75: U12.8@3673.98,4515.08 U12.7@3673.98,4558.39 v7(3673.98,4601.69)
IO0: H2.4 R82.2 U61.25 | length 5433.6
  Top Layer w10: v2(3310,4285) 3310,4291.08 3415,4396.08 3415,4650 3470,4705 3470,4775 3340,4905 3275,4905 3250,4930 3250,5100 3275,5125 3275,6150 3305,6180 3305,6340 3275,6370 3275,6595 3305,6625 3580,6625 v2(3995,6210) ; v2(3811.53,3541.53) 4028.07,3541.53 H2.4@4051.54,3565
  Bottom Layer w10: v2(3310,4285) 3380,4215 3390,4215 3470,4135 3470,3975 3405.98,3910.98 3323.38,3910.98 3220,3807.61 3220,3660 3338.47,3541.53 v2(3811.53,3541.53) ; v2(3995,6210) R82.2@4050.34,6210 4050.34,6179.66 4055,6175 4140,6175 4155,6190 U61.25@4205.67,6190
IPS_PWM: R62.2 TP18.1 U44.134 | length 2688.8
  Top Layer w10: v1(4772.03,4885.67) 4832.69,4825 4875,4825 4884.49,4834.49 4884.49,5021.43 4915,5051.94 4915,5675 4999.03,5759.03 v1(4999.03,5879.03) 5115.97,5879.03 5145,5850 5181.69,5850 5184.41,5852.72 5186.91,5852.72 5196.69,5862.5 5196.69,5865 v1(5323.57,5991.88) ; v1(5750,6625) 5750,6628.87 TP18.1@5773.86,6652.73
  Inner2 w10: v1(5323.57,5991.88) 5331.88,5991.88 5885,6545 5885,6600 5870,6615 5760,6615 v1(5750,6625)
  Bottom Layer w10: v1(4772.03,4885.67) 4774.27,4885.67 4791.27,4868.67 U44.134@4791.27,4864.94
IPS_RST: FPC1.10 TP19.1 U44.117 | length 2855.7
  Top Layer w10: v1(5355,6230) 5425,6300 5755,6300 5898.62,6443.62 TP19.1@5898.62,6653.47
  Bottom Layer w10: U44.117@5027.9,5101.57 5054.42,5075.05 5145.05,5075.05 5152.01,5082.01 5347.99,5082.01 5354.95,5075.05 5550.05,5075.05 5680,5205 5680,5903.19 v1@5355,6228.19 ; FPC1.10@5254.35,6302.48 5280.71,6302.48 v1@5355,6228.19 ; v1(5355,6230) v1@5355,6228.19
IPS_TE: FPC1.39 U44.96 | length 874.1
  Inner2 w10: v1(5027.5,5541.84) 5027.5,5544.34 5038.16,5555 5054.58,5555 5061.65,5562.07 5061.65,5602.93 5068.72,5610 5114.58,5610 5121.65,5602.93 5121.65,5562.07 5128.72,5555 5174.58,5555 5181.65,5562.07 5181.65,5602.93 5188.72,5610 5234.58,5610 5241.65,5602.93 5241.65,5562.07 5248.72,5555 5310,5555 5325,5540 v1(5325,5530)
  Bottom Layer w10: U44.96@4972.22,5494.1 5019.96,5541.84 v1(5027.5,5541.84) ; FPC1.39@5254.35,5731.61 5255.96,5730 5295,5730 5327.5,5697.5 5327.5,5617.5 5360,5585 5360,5550 5340,5530 v1(5325,5530)
IR_RX: LED6.1 R75.2 U61.13 | length 1011.4
  Top Layer w10: v1(4985,6240) 5010,6265 5010,6385 v1(5220,6595)
  Bottom Layer w10: U61.13@4914.33,6240 v1(4985,6240) ; R75.2@5087.93,6847.59 R75.2@5095.34,6855 5095.34,6819.66 5105,6810 5135,6810 5175,6770 5175,6705 5200,6680 5200,6605 5210,6595 v1(5220,6595)
  Bottom Layer w29.53: LED6.1@5034.68,6960.81 5034.69,6895.31 5075,6855 R75.2@5095.34,6855
IR_TX: R77.1 U60.1 U61.16 | length 2105.6
  Top Layer w19.68: v6(4830,6785) 5185,6785 v6(5295,6895)
  Inner2 w19.68: v6(5384.7,6829.27) 5630.29,6583.68 v6(5836.41,6583.68)
  Bottom Layer w19.68: v6(4830,6785) 4730,6685 4730,6455 4660,6385 4660,6234.54 4799.54,6095 4909.33,6095 U61.16@4914.33,6090 ; v6(5295,6895) 5345.01,6895 U60.1@5385,6855
LED7_2: Q3.2 U60.3 | length 170.9
  Bottom Layer w39.37: U60.3@5584.7,6814.27 5584.7,6745.3 5645.01,6684.99 Q3.2@5645.01,6668.4
NFC_CS: FPC4.15 U44.75 | length 1134
  Top Layer w10: v1(3815,5555.16) 3835.16,5555.16 v1(3930,5650)
  Inner2 w10: v1(3930,5650) 4082.71,5650 4090,5657.29 4357.29,5657.29 4565,5865 v1(4610,5865)
  Bottom Layer w10: FPC4.15@3775.53,5555.16 v1(3815,5555.16) ; v1(4610,5865) 4611.63,5863.37 4611.63,5783.48 4635.22,5759.89 4648.88,5759.89 4675.4,5786.41 U44.75@4679.91,5786.41
NFC_IRQ: FPC4.14 U44.45 | length 471.8
  Top Layer w10: v1(3815,5535.47) 3825.47,5525 4120,5525 4130,5515 v1(4145,5515)
  Bottom Layer w10: FPC4.14@3775.53,5535.47 v1(3815,5535.47) ; v1(4145,5515) 4132.68,5502.68 4132.68,5472.32 4162.1,5442.9 U44.45@4162.1,5438.43
NRST: C31.1 H1.5 U29.1 U44.25 | length 2484.3
  Top Layer w10: U29.1@3415,3700.34 3365.34,3700.34 3365,3700 3355,3700 3275,3780 3275,3890 3350,3965 3440,3965 3535,4060 3535,4195 3725,4385 3725,4550 3860,4685 3860,4821.39 3918.61,4880 v1(3940,4880)
  Top Layer w39.37: U29.1@3415,3700.34 3425.34,3690 H1.5@3523.47,3690 3495,3718.47 C31.1@3495,3757.44
  Inner2 w10: v1(3940,4880) 3968.46,4908.46 3968.46,4927 3987.91,4946.44 v1(3987.91,5008.9)
  Inner3 w10: v1(3987.91,5008.9) 3987.91,5031.52 3991.5,5035.1 3991.5,5083.5 3977.6,5097.4 3977.6,5130 3987.6,5140 4065,5140 4108.31,5183.31 v1(4211.8,5183.31)
  Bottom Layer w10: U44.25@4203.86,5059.81 4233.7,5089.65 4233.7,5108.7 4211.8,5130.59 v1(4211.8,5183.31)
OSC32_IN: R56.2 X2.2 | length 123
  Top Layer w10: X2.2@4130,4895.47 4154.53,4895.47 4175,4875 4230.34,4875 R56.2@4240.34,4865
OSC32_OUT: R55.2 X2.1 | length 112.6
  Top Layer w10: X2.1@4130,4804.53 4236.15,4804.53 R55.2@4240.68,4800
OSC-IN: R85.2 U44.23 | length 291.6
  Inner3 w10: v1(4010,4971.42) 4031.42,4950 v1(4145,4950)
  Bottom Layer w10: v1(4010,4971.42) 4019.66,4981.08 R85.2@4019.66,4990 ; v1(4145,4950) 4157.39,4950 4195,4987.61 4195,4995.27 U44.23@4231.7,5031.97
OSC-OUT: U44.24
OUTL: C2.2 C77.2 R71.1 | length 906.2
  Top Layer w10: C2.2@4490.51,4805.51 4490.51,4804.49 4520,4775 4520,4722.61 4578.9,4663.7 4578.9,4623.97 4586.78,4616.1 4631.1,4616.1 4640.31,4625.31 4640.31,4664.48 4661.82,4685.98 4738.59,4685.98 4764.36,4711.76 4764.36,4715.69 4779.26,4730.59 4783.19,4730.59 4792.61,4740 4830,4740 4860,4770 4905,4770 4920,4785 5075.34,4785 5075.34,4799.03 C77.2@5019.37,4855
OUTR: C76.2 C86.2 R72.1 | length 411.7
  Top Layer w10: C86.2@4754.49,4745.51 4755.71,4745.51 v2(4756.26,4744.96) ; v2@4853.9,4731.1 v2(4855.16,4729.84) 5075.34,4729.84 5075.34,4660.97 C76.2@5064.37,4650
  Bottom Layer w10: v2(4756.26,4744.96) 4770.12,4731.1 v2@4853.9,4731.1
PUSH_A: R51.1 SW4.A U44.50 | length 3261.7
  Top Layer w3.94: v1(3815,4545) 3800,4530 3800,4435 3850,4385 v1(3950,4385) ; v1(3985,5600) 4059.54,5600 v1(4081.65,5577.89) ; v1(4125,4100) 4125,3910 4164.84,3870.16 4620.16,3870.16 4639.66,3889.66 R51.1@4639.66,3925
  Top Layer w10: R51.1@4649.03,3927.91 4652.11,3924.83 4947.87,3924.83 SW4.A@4950.95,3927.91
  Inner2 w3.94: v1(3950,4385) 3950,4275 v1(4125,4100)
  Inner3 w3.94: v1(3815,4545) 3815,4620 3705,4730 3705,5400 3905,5600 v1(3985,5600)
  Bottom Layer w3.94: v1(4081.65,5577.89) 4084.54,5575 4155.92,5575 4222.89,5508.03 U44.50@4231.7,5508.03
PUSH_B: R50.1 SW4.B U44.53 | length 4963.2
  Top Layer w10: v1(5045,6035) 5045,6067.39 5161.62,6184.02 5205,6184.02 5224.02,6165 5224.02,6138.38 5354.02,6008.38 5354.02,5614.02 v1(5320,5580) ; SW4.B@5317.09,4175.94 R50.1@5400.34,4175 ; R50.1@5400.34,4175 5365,4139.66 5365,4085 5375,4075 5430,4075 5435,4080 5435,4106.48 5448.52,4120 5530,4120 5555,4145 5555,4200 5565,4210 v1(5660,4210) ; v1(5530,5410) 5530,5257.61 5705,5082.61 v1(5705,4965)
  Bottom Layer w10: U44.53@4273.46,5549.78 4235,5588.24 4235,5660 4212.5,5682.5 4212.5,5822.5 4520,6130 4710,6130 4780,6060 4800,6060 4833.91,6026.09 4833.91,5919.63 4856.5,5897.05 4967.05,5897.05 5000,5930 5000,6010 5015,6025 5035,6025 v1(5045,6035) ; v1(5320,5580) 5305,5565 5305,5520 5315,5510 5510,5510 5520,5500 5520,5420 v1(5530,5410) ; v1(5660,4210) 5695,4245 5845,4245 5887.5,4287.5 5887.5,4812.5 5860,4840 5830,4840 v1(5705,4965)
PUSH_C: R53.2 SW4.C U44.90 | length 3744.1
  Top Layer w3.94: v1(5150,5285) 5175,5310 5175,5441.4 5184.66,5451.06 5541.62,5451.06 5620,5372.68 5620,5330 5682.96,5267.04 5713.71,5267.04 5730,5250.74 5730,5060.33 5717.95,5048.28 5717.95,4984.84 5745,4957.8 5812.03,4957.8 5844.83,4925 v1(5860,4925) ; v1(5330,4515) 5350.34,4535.34 R53.2@5350.34,4555 ; v1(5525,4495) 5525,4355 5565,4315 5645,4315 v1(5735,4225)
  Top Layer w10: SW4.C@5069.06,4542.09 5081.97,4555 R53.2@5350.34,4555
  Inner3 w3.94: v1(4791.77,5305) 4836.77,5305 v1(4848.39,5293.39) ; v1(5330,4515) 5350,4495 v1(5525,4495)
  Bottom Layer w3.94: v1(4791.77,5305) 4791.77,5330.85 4797.24,5336.31 4797.24,5454.16 4834.09,5491.01 4834.09,5509.21 4850.41,5525.52 4850.41,5539.33 U44.90@4888.7,5577.62 ; v1(4848.39,5293.39) 4856.77,5285 4966.68,5285 4969.63,5282.05 5056.87,5282.05 5059.82,5285 v1(5150,5285) ; v1(5735,4225) 5843.32,4225 5900.45,4282.13 5900.45,4817.87 5860,4858.32 v1(5860,4925)
PUSH_CTRL: R73.1 SW4.5 U44.132 | length 2547.3
  Top Layer w3.94: v1(4747.87,4553.19) 4747.87,4515.99 4880,4383.87 4880,4350 4955,4275 v1(5120,4275) ; v1(4860,5075) 4869.02,5065.98 4869.02,4863.2 v1(4864.13,4858.31) ; v1(5365,4045) 5365.34,4045.34 R73.1@5400,4045.34
  Top Layer w10: SW4.5@5049.37,3960.2 5314.86,3960.2 R73.1@5400,4045.34
  Inner2 w3.94: v1(4747.87,4553.19) 4763.19,4553.19 4766.06,4556.06 4766.06,4668.92 4802.05,4704.9 4802.05,4765.58 4800,4767.63 4800,4800 4810,4810 4815.83,4810 v1(4864.13,4858.31)
  Inner3 w3.94: v1(4606.93,5111.93) 4656.93,5111.93 4665,5120 4806.93,5120 4851.93,5075 v1(4860,5075)
  Bottom Layer w3.94: v1(5120,4275) 5120,4260.16 5109.84,4250 5109.84,4173.22 5241.53,4041.53 5361.53,4041.53 v1(5365,4045)
  Bottom Layer w10: v1(4606.93,5111.93) 4659.02,5059.85 4659.02,5041.84 4725.86,4975 4740,4975 4780,4935 4780,4934 4794.7,4919.3 4794.7,4917.18 U44.132@4819.1,4892.78
PUSH_D: R52.2 SW4.D U44.91 | length 2879.6
  Top Layer w3.94: R52.2@4619.66,4295 4619.66,4265.34 4635,4250 4735,4250 v1(4750,4265) ; v1(5050,5255) 5070,5235 5308.94,5235 5413.94,5130 5549.52,5130 5582.2,5097.31 5582.2,5057.2 v1(5550,5025)
  Top Layer w10: R52.2@4619.66,4295 SW4.D@4702.9,4294.1 ; v1(5160,4386.1) 5218.9,4386.1 v1(5219.47,4385.53)
  Inner3 w3.94: v1(4809.17,5249.66) v1(4865,5249.66) ; v1(5219.47,4385.53) 5245,4411.05 5245,4510 5295,4560 5295,4624.83 5315.08,4644.92 5349.24,4644.92 5365,4660.68 5365,4694.83 5476.64,4806.48 5476.64,4951.64 v1(5550,5025)
  Inner3 w10: v1(4750,4265) 5038.9,4265 v1(5160,4386.1)
  Bottom Layer w3.94: v1(4809.17,5249.66) 4809.17,5452.06 4844.02,5486.9 4844.02,5505.1 U44.91@4902.62,5563.7 ; v1(4865,5249.66) 4865,5260.08 4880,5275.08 4962.57,5275.08 4965.53,5272.13 5042.87,5272.13 5050,5265 v1(5050,5255)
QSPI_CLK: R44.2 U44.14 | length 1250.6
  Top Layer w10: v1(4132.32,4485) 4132.32,4460 4157.32,4435 4165,4435 4172.07,4427.93 4302.93,4427.93 4327.04,4452.04 R44.2@4327.04,4465
  Inner3 w3.94: v1(4022.5,4747.5) 4022.5,4768.89 4031.69,4778.09 4031.69,4791.91 4025,4798.61 4025,4807.56 4028.94,4811.5 4170.05,4811.5 v1(4187.41,4828.86)
  Bottom Layer w3.94: v1(4187.41,4828.86) 4192.7,4828.86 4198.09,4834.25 4284.52,4834.25 U44.14@4356.97,4906.7
  Bottom Layer w10: v1(4022.5,4747.5) 4056.69,4713.31 4091.69,4713.31 4102.05,4702.95 4102.05,4674.46 4079.14,4651.56 4050,4651.56 4042.93,4644.49 4042.93,4614.46 4050,4607.39 4077.61,4607.39 4102.05,4582.95 4102.05,4557.05 4069.51,4524.51 4055.37,4524.51 4042.93,4512.07 4042.93,4475.14 4063.06,4455 4109.12,4455 4130,4475.88 4130,4482.68 v1(4132.32,4485)
QSPI_IO0: R43.2 U44.10 | length 999.8
  Bottom Layer w3.94: R43.2@4372.04,4450 4370,4447.96 4370,4435 4360,4425 4338.52,4425 4322.53,4409.02 4178.38,4409.02 4145.98,4441.41 4145.98,4490.66 4115,4521.64 4115,4675 4132.72,4692.72 4287.28,4692.72 4312.95,4667.05 4353.61,4667.05 4373.5,4686.94 4373.5,4713.5 4385,4725 4385,4742.11 4355.67,4771.44 4355.67,4794.04 U44.10@4412.65,4851.02
QSPI_IO1: R42.1 U44.11 | length 1148.9
  Bottom Layer w3.94: R42.1@4012.04,4875 4012.04,4858.72 3955.37,4802.05 3935,4802.05 3930,4797.05 3930,4715 3934.26,4710.74 3946.12,4710.74 3950,4714.61 3950,4785 4005.31,4840.31 4009.69,4840.31 4014.7,4835.3 4014.7,4831.77 3980,4797.07 3980,4713.94 3983.94,4710 3995,4710 4000,4715 4000,4800 4005,4805 4025,4805 4029.2,4800.8 4029.2,4760.12 4045.66,4743.66 4288.66,4743.66 4300,4755 4300,4767.27 4334.78,4802.05 4348.97,4802.05 4372.24,4825.31 4372.24,4838.45 U44.11@4398.73,4864.94
QSPI_IO2: R109.2 U44.12 | length 1158.1
  Bottom Layer w3.94: R109.2@4127.96,4875 4127.83,4874.87 4127.83,4869.3 4136.99,4860.13 4136.99,4850.13 4130.93,4844.07 4122.6,4844.07 4118.79,4840.27 4118.79,4836.16 4118.66,4836.02 4118.66,4835.13 4121.44,4832.35 4134.27,4832.35 4136.99,4829.63 4136.99,4817.26 4134.87,4815.13 4099.87,4815.13 4098.18,4813.45 4098.18,4801.82 4099.51,4800.49 4152.2,4800.49 4156.14,4796.55 4156.14,4790.13 4152.2,4786.2 4093.8,4786.2 4089.87,4790.13 4074.87,4790.13 4069.05,4784.31 4067.95,4784.31 4067.82,4784.18 4056.5,4784.18 4048.37,4792.31 4048.37,4803.63 4059.87,4815.13 4059.87,4829.57 4057.08,4832.35 4052.19,4832.35 4049.87,4830.03 4049.87,4820.13 4044.87,4815.13 4039.87,4815.13 4034.87,4820.13 4034.87,4845.13 4044.87,4855.13 4064.87,4855.13 4069.87,4850.13 4069.87,4841.79 4074.87,4836.79 4083.21,4836.79 4092.15,4845.74 4092.15,4860.74 4081.42,4871.47 4075.79,4871.47 4075.66,4871.34 4064.34,4871.34 4064.21,4871.47 4053.53,4871.47 4050.25,4874.75 4050.25,4897.82 4047.94,4900.13 4034.05,4900.13 4031.13,4897.22 4031.13,4856.39 4024.87,4850.13 4024.87,4819.16 4039.13,4804.9 4039.13,4785 4048.17,4775.95 4064.05,4775.95 4084.87,4755.13 4150.27,4755.13 4180.96,4785.83 4295.83,4785.83 4310,4800 4310,4817.85 4328.94,4836.79 4341.79,4836.79 4383.86,4878.86 U44.12@4384.81,4878.86
QSPI_IO3: R45.1 U44.13 | length 1274.3
  Top Layer w10: R45.1@3912.04,4465 3922.04,4455 3965,4455 v1(3985,4475)
  Inner2 w3.94: v1(4050.98,4695) 4053.66,4697.68 4053.66,4754.29 v1(4056.69,4757.32)
  Inner3 w3.94: v1(4056.69,4757.32) 4064.72,4765.35 4138.82,4765.35 v1(4146.01,4772.53)
  Bottom Layer w3.94: v1(4146.01,4772.53) 4148.54,4770 4151.1,4770 4176.85,4795.75 4291.72,4795.75 4300.08,4804.11 4300.08,4821.96 U44.13@4370.9,4892.78
  Bottom Layer w10: v1(3985,4475) 4003.7,4475 4010,4481.3 4010,4496.06 4001.06,4505 3945,4505 3935,4515 3935,4530 3947.5,4542.5 4014.11,4542.5 4024.99,4553.37 4024.99,4567.51 4012.5,4580 3944.76,4580 3935,4589.76 3935,4608.58 3943.92,4617.5 4022.5,4617.5 4025,4620 4025,4642.5 4020,4647.5 3945,4647.5 3933.75,4658.75 3933.75,4678.75 3950,4695 3975,4695 3985,4685 4044.08,4685 4050.98,4691.9 v1(4050.98,4695)
QSPI_NCS: R46.1 U26.2 U44.127 | length 1426.5
  Top Layer w10: v1(3785,4806.74) 3785,4800.34 U26.2@3830.34,4755
  Inner2 w10: v1(3785,4806.74) 3785,4880 3945,5040 3965,5040 3970.25,5034.75 v1(3970.25,5027.69)
  Inner3 w10: v1(3970.25,5027.69) 3970.91,5027.04 3970.91,4996.73 3979.52,4988.11 4094.56,4988.11 4126.45,5020 4141.4,5020 4156.4,5005 4485,5005 4505,4985 4640,4985 4678.99,5023.99 v1(4791.75,5023.99)
  Bottom Layer w10: v1(4791.75,5023.99) 4827.09,5023.99 U44.127@4888.7,4962.38
RESET#: R111.1 U28.A4 U44.124 | length 958.4
  Inner2 w10: v2(4885.83,5050.83) 4885.83,5041.33 5001.89,4925.27 5001.89,4915.63 5011.89,4905.63 5042.36,4905.63 5091.73,4955 5335.34,4955 v2(5340.34,4950) 5245.3,4854.96 v2(5065.04,4854.96)
  Bottom Layer w10: v2(4885.83,5050.83) 4885.83,5048.76 U44.124@4930.46,5004.13 ; U28.A4@5057.84,4828.52 5057.84,4847.76 v2(5065.04,4854.96) ; R111.1@5330.34,4950 R111.1@5331.1,4950
RTC_INT: R18.1 U16.3 U44.122 | length 1210.4
  Inner2 w3.94: v1(4986.43,4999.96) 4991.72,4999.96 5020.1,4971.58 5058.42,4971.58 5080.78,4993.94 5105.62,4993.94 5120.82,5009.14 5120.82,5015.82 5157.95,5052.95 5287.05,5052.95 v1(5320,5020)
  Inner2 w19.68: v2(5595,4732.02) 5595,4780 5644.03,4829.03 v2(5679.03,4829.03)
  Bottom Layer w3.94: U44.122@4958.3,5031.97 4986.43,5003.84 v1(4986.43,4999.96) ; v1(5320,5020) 5357.95,4982.05 5412.95,4982.05 5430,4965 5559.15,4965 5559.34,4964.81 5570.66,4964.81 5570.85,4965 5685,4965 5760,4890 5760,4860 5729.03,4829.03 v2(5679.03,4829.03)
RTC_SCL: R14.1 U16.16 U44.54 | length 3418.2
  Top Layer w3.94: v1(4825.3,5187.6) 4861.2,5151.69 v1(4880.3,5151.69) ; v1(4935.3,4925) 4935,4924.7 4935,4905 4945,4895 4970,4895 4980,4885 4980,4825 4991.3,4813.7 v1(5015.3,4813.7) ; v1@5095,4490 5115.3,4469.7 v1(5115.3,4365)
  Inner2 w3.94: v1(4343.45,5383.16) 4437.57,5383.16 v1(4474.03,5346.69) ; v1(5025.3,4708.15) 5025.3,4684.7 5095.3,4614.7 5095.3,4577.21 5112.45,4560.06 5112.45,4524.12 5095.3,4506.97 v1(5095.3,4490)
  Inner3 w3.94: v1(4474.03,5346.69) 4478.09,5342.64 4478.09,5323.9 4614.39,5187.6 v1(4825.3,5187.6) ; v1(4880.3,5151.69) 4901.69,5151.69 4945.08,5195.08 5165.89,5195.08 5192.28,5168.69 5192.28,5051.31 5152.5,5011.53 5152.5,5001.69 5118.01,4967.21 4972.21,4967.21 4935.3,4930.3 v1(4935.3,4925) ; v1(5015.3,4813.7) 5008.7,4813.7 4964.55,4769.55 4964.55,4735.45 4975,4725 5008.44,4725 v1(5025.3,4708.15)
  Bottom Layer w3.94: U44.54@4287.38,5563.7 4315,5536.08 4315,5411.61 v1(4343.45,5383.16) ; v1@5115,4365 5099.92,4349.92 5099.92,4169.11 5239.11,4029.92 5405.89,4029.92 5555.08,4179.11 5555.08,4212.84 5544.41,4223.5 5516.5,4223.5 5464.03,4275.97 R14.1@5440.97,4275.97
  Bottom Layer w19.68: R14.1@5440.97,4275.97 5485,4320 U16.16@5485,4357.98
RTC_SDA: R16.1 U16.15 U44.55 | length 3637.1
  Top Layer w3.94: v1(4825.3,5210) 4865.3,5170 v1(4893.31,5170) ; v1(4955.15,4924.85) 4955.15,4909.77 4960,4904.92 5054.92,4904.92 5085,4935 5110.57,4935 5130,4915.57 v1(5130,4893.94) ; v1@5090,4465 5105.37,4449.63 5105.37,4385.08 v1(5090.3,4370)
  Inner2 w3.94: v1(4352.87,5403.34) 4446.95,5403.34 v1(4495.3,5355) ; v1(5050,4695) 5105.22,4639.78 5105.22,4583.27 5122.37,4566.12 5122.37,4497.07 v1(5090.3,4465)
  Inner3 w3.94: v1(4495.3,5355) 4488.01,5347.71 4488.01,5328.01 4611.1,5204.92 4820.22,5204.92 v1(4825.3,5210) ; v1(4893.31,5170) 4905.97,5170 4940.97,5205 5170,5205 5202.2,5172.8 5202.2,5047.2 5162.42,5007.42 5162.42,4997.58 5122.12,4957.29 5038.68,4957.29 5013.82,4932.44 5013.82,4908.82 5005.24,4900.24 4969.76,4900.24 4955,4915 4955,4924.7 v1(4955.15,4924.85) ; v1(5050,4695) 5050,4700 5048.96,4701.04 5048.96,4706.61 5020.65,4734.92 4979.11,4734.92 4974.47,4739.56 4974.47,4765.44 5004.03,4795 5021.45,4795 5042.44,4815.98 5050.98,4815.98 5065,4830 5085,4830 5095,4840 5095,4858.94 v1(5130,4893.94)
  Bottom Layer w3.94: U44.55@4301.3,5577.62 4325,5553.92 4325,5524.25 4324.92,5524.18 4324.92,5431.3 v1(4352.87,5403.34) ; v1@5090,4370 5090,4165 5235,4020 5410,4020 5565,4175 5565,4216.95 R16.1@5525.97,4255.97
  Bottom Layer w19.68: R16.1@5525.97,4255.97 5535,4265 U16.15@5535,4357.98
RTC_VCC: C10.2 C11.1 R9.1 R14.2 R16.2 R17.2 R18.2 U16.2 | length 1231.4
  Bottom Layer w19.68: R17.2@5381.17,4466.17 5415,4432.34 5415,4350 5385,4320 5385,4248.05 R14.2@5399.03,4234.03 ; R9.1@5475.97,4840.97 5496.95,4820 C11.1@5547.44,4820 ; 5535,4630 U16.2@5535,4732.02 5535,4780 5547.44,4792.44 C11.1@5547.44,4820 ; R18.2@5720.97,4870.97 5720.97,4894.03 5670,4945 5570,4945 5547.44,4922.44 C10.2@5547.44,4900 C11.1@5547.44,4820
  Bottom Layer w29.53: R14.2@5399.03,4234.03 5419.03,4214.03 R16.2@5484.03,4214.03
  Bottom Layer w39.37: R17.2@5366.17,4466.17 5426.17,4466.17 5535,4575 5535,4630
RWDS: R108.1 U44.35 | length 1755.3
  Inner2 w10: v1(4844.92,4786.69) 4866.54,4786.69 4883.58,4769.65 5011.01,4769.65 5013.82,4766.84 5083.96,4766.84 5086.77,4769.65 5124.65,4769.65 5152.67,4797.67 5152.67,4809.02 5159.74,4816.09 5204.6,4816.09 5211.67,4809.02 5211.67,4803.07 5219.74,4795 5265.6,4795 5273.64,4803.05 5273.64,4809.02 5280.72,4816.09 5325.6,4816.09 5332.67,4809.02 5332.67,4802.07 5339.74,4795 v1(5350,4795)
  Inner3 w10: v1(4781.11,4958.39) 4785,4954.5 4785,4942.82 4804.7,4923.11 4804.7,4838.9 4844.92,4798.69 v1(4844.92,4786.69)
  Bottom Layer w10: U44.35@4064.67,5199.01 4091.19,5225.53 4155.97,5225.53 4174.43,5207.07 4222.82,5207.07 4229.89,5214.14 4229.89,5249.89 4247.22,5267.22 4282.82,5267.22 4289.89,5260.15 4289.89,5214.14 4296.96,5207.07 4535.4,5207.07 4675,5067.47 4675,5049.5 4732.04,4992.45 4747.04,4992.45 v1(4781.11,4958.39) ; R108.1@5320,4787.04 5342.04,4787.04 v1(5350,4795)
RXD0: FPC4.22 H2.2 U61.34 | length 5434.9
  Top Layer w10: v1(3425,5865) 3425,5842.95 v1(3575,5692.95) ; v1(3860,3335) 3890,3365 H2.2@4051.54,3365
  Inner2 w10: v1(3255.65,4880.65) 3255.65,3939.35 v1(3860,3335)
  Bottom Layer w10: v1(3255.65,4880.65) 3236.3,4900 3236.3,5118.7 3341.3,5223.7 3341.3,5348.7 3400.98,5408.38 3400.98,5891.07 ; v1(3425,5865) 3425,5867.05 3400.98,5891.07 ; v1(3575,5692.95) FPC4.22@3775.53,5692.95 ; U61.34@4205.67,6640 4090,6640 4056.56,6673.44 3923.96,6673.44 3868.38,6729.02 3326.62,6729.02 3250.98,6653.38 3250.98,6400 3290,6360.98 3341.62,6360.98 3400.98,6301.62 3400.98,5891.07
SCK_A: U44.4 U61.11 | length 2729.4
  Top Layer w10: v1(4589.02,5094.58) 4589.59,5094.02 4626.99,5094.02 4634.02,5101.04 ; 4634.02,5050 4634.02,5101.04 ; v1(4685,6260) 4556.72,6260 4515,6218.28 4515,5966.72 4576.72,5905 4690,5905 4700,5895 4700,5851.39 4740,5811.39 4740,5692.06 4626.96,5579.02 4561.62,5579.02 4514.02,5531.41 4514.02,5478.38 4530.45,5461.94 4713.07,5461.94 4815,5360.01 4815,5304.62 4634.02,5123.64 4634.02,5101.04
  Bottom Layer w10: U44.4@4496.17,4767.51 4542.68,4814.02 4581.63,4814.02 4635,4867.39 4635,4897.39 4681.78,4944.18 4681.78,4986.91 4641.85,5026.85 4641.85,5041.76 v1(4589.02,5094.58) ; v1(4685,6260) 4712.39,6260 4758.38,6305.98 4820.98,6305.98 4855,6340 U61.11@4914.33,6340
